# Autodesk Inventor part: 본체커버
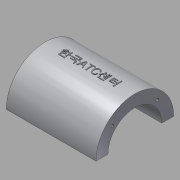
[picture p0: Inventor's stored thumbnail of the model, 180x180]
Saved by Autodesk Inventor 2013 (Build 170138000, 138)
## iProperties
Created: 2015-12
Part Number: 본체커버
Material: 알루미늄 6061
Document SubType Name: Modeling
Designer: mduedu
Density: 2.71 g/cm^3
Mass: 174.994 g
Surface Area: 167.085 cm^2
Volume: 64.5736 cm^3
Author: mduedu
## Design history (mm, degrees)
sketch "스케치1"
  geometry: L1 (45, 40)-(-45, 40); L2 (-45, 40)-(-45, -40); L3 (-45, -40)-(45, -40); L4 (45, -40)-(45, 40); L5 (45, 40)-(-45, -40); L6 (-45, 40)-(45, -40); 1 further point
  constraints: 12 end point, 2 midpoint, 2 parallel, 1 horizontal, 1 perpendicular
  dimensions: "d0" = 90 distance of L2.end L3.end; "d2" = 80 distance of L1.end L2.end
extrude "돌출1" new body sketch "스케치1" distance "d3" = 10; taper "d4" = 0 deg
sketch "스케치2"
  geometry: L1 (0, 40)-(0, -40) reference; C1 r 32.5 at (80, 0); 1 further point
  constraints: 1 centre point
  dimensions: "d5" = 65 diameter of C1; "d6" = 80 distance from line of C1.centre L1
extrude "돌출2" join sketch "스케치2" stored distance "d7" = 75; taper "d8" = 0 deg
sketch "스케치3"
  geometry: L1 (-27.5, -20)-(27.5, -20); L2 (27.5, -20)-(27.5, 20); L3 (27.5, 20)-(-27.5, 20); L4 (-27.5, 20)-(-27.5, -20); L5 (-27.5, -20)-(27.5, 20); L6 (27.5, -20)-(-27.5, 20); 1 further point
  constraints: 12 end point, 2 midpoint, 2 parallel, 1 horizontal, 1 perpendicular
  dimensions: "d9" = 55 distance of L2.end L3.end; "d11" = 40 distance of L1.end L2.end
extrude "돌출3" new body sketch "스케치3" stored distance "d12" = 75; taper "d13" = 0 deg
fillet "모깎기1"
fillet "모깎기2"
feature "결합1"
  node "솔리드2"
fillet "모깎기3" dims "d14" = 10
sketch "스케치4"
  geometry: L1 (-37.5, 47.5)-(37.5, 47.5) reference; L2 (35, 10)-(45, 10) reference; L3 (32.5, 47.5)-(40, 10); L4 (37.5, 47.5)-(37.5, 112.5) reference; L5 (45, 10)-(45, 0) reference; 1 further point
  constraints: 2 end point, 1 midpoint, 1 point on line
  dimensions: "d15" = 5 distance from line of L3.start L4; "d16" = 5 distance from line of L3.end L5
sketch "스케치5"
  geometry: L1 (10, 40)-(10, 30) reference; L2 (10, 35)-(56.569, 22.522); L3 (0, 40)-(10, 40) reference; 2 further points
  constraints: 2 end point, 1 midpoint, 2 other
  dimensions: "d17" = 5 distance from line of L2.start L3; "d18" = 15 deg angle of L2 L3
feature "리브1" dims "d19" = 1, "d20" = 6, "d21" = 0, "d22" = 0, "d23" = 1, "d24" = 1
feature "리브2" dims "d25" = 1, "d26" = 6, "d27" = 0, "d28" = 0, "d29" = 1, "d30" = 1
fillet "모깎기4" dims "d31" = 2
fillet "모깎기5" dims "d32" = 2
fillet "모깎기6" dims "d33" = 2
sketch "스케치6"
  geometry: A1 r 10 centre (-35, 30) between (-35, 40) and (-45, 30) reference; A2 r 10 centre (35, 30) between (45, 30) and (35, 40) reference; A3 r 10 centre (35, -30) between (35, -40) and (45, -30) reference; A4 r 10 centre (-35, -30) between (-45, -30) and (-35, -40) reference; 5 further points
  constraints: 4 coincident
hole "구멍1" sketch "스케치6" at (-35, 30), (35, 30), (35, -30), (-35, -30) diameter "d34" = 7; stored, may be unused: countersink angle "d38" = 90 deg, drill point angle "d40" = 118 deg; dims "d35" = 6, "d36" = 12, "d37" = 3, "d39" = 8
fillet "모깎기7" dims "d41" = 2
hole "구멍2" diameter "d44" = 45; stored, may be unused: countersink angle "d48" = 90 deg, drill point angle "d50" = 118 deg; dims "d42" = 10, "d43" = 10, "d45" = 6, "d46" = 4, "d47" = 2, "d49" = 8
sketch "스케치7" dims "d52" = 26.5
  geometry: L1 (0, 0)-(32.5, 0); L2 (0, 0)-(22.981, 22.981); A1 r 32.5 centre (0, 0) between (32.5, 0) and (22.981, 22.981) reference; 3 further points
  constraints: 4 end point, 2 point on circle, 1 coincident, 1 horizontal, 1 point on line, 3 other
  dimensions: "d51" = 45 deg angle of L2 L1
hole "구멍3" sketch "스케치7" at (18.738, 18.738) diameter "d54" = 2.459; stored, may be unused: countersink angle "d58" = 90 deg, drill point angle "d60" = 118 deg; dims "d55" = 8, "d56" = 4, "d57" = 2, "d59" = 10
sketch "스케치13"
  geometry: L1 (-45, 80)-(105, 80); L2 (105, 80)-(105, -30); L3 (105, -30)-(-45, -30); L4 (-45, -30)-(-45, 80); L5 (0, 0)-(60, 0) reference; C1 r 32.5 at (30, 80) reference; 1 further point
  constraints: 8 end point, 2 parallel, 1 coincident, 1 horizontal, 1 midpoint, 1 perpendicular
  dimensions: "d99" = 30 distance between parallel lines of L3 L5; "d126" = 150 distance between parallel lines of L2 L4
extrude "돌출8" cut sketch "스케치13" stored distance "d97" = 10; taper "d98" = 0 deg
node "작업 평면2"
sketch "스케치14"
  geometry: 2 further points
  constraints: 1 coincident, 1 other
feature "엠보싱1" sketch "스케치14" dims "d102" = 0.5, "d103" = 0
sketch "스케치18"
  geometry: L1 (0, -10)-(0, 0) reference; L2 (75, 0)-(75, -10) reference; L3 (0, -5)-(75, -5); C1 r 1.5 at (13, -5); 1 further point
  constraints: 2 end point, 2 midpoint, 1 centre point, 1 point on line
  dimensions: "d127" = 3 diameter of C1; "d128" = 13 distance from line of L1 C1.centre
extrude "돌출9" cut sketch "스케치18" distance "d129" = 2; taper "d130" = 0 deg
chamfer "모따기2" distance "d131" = 0.5; stored, may be unused: second distance "d132" = 2, angle "d133" = 45 deg
fillet "모깎기12" dims "d134" = 0.1
node "솔리드1"
mirror "대칭1"
mirror "대칭2"
pattern_circular "원형 패턴1" dims angle "d62" = 360 deg
mirror "대칭3"
mirror "대칭5"
mirror "대칭6"
